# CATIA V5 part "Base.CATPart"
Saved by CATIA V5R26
Part number: Base
Bounding box of the stored display mesh (mm): x -23.876 to 23.876, y 0 to 88.9, z 0 to 54.102
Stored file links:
  D:\_Deepak\CATIA\CATIA V5 2015 Parts Files\EXE Files\Exercises\c13_catia_v5_6r2015_exr\C13Exr01_cat_v5-6r2015\Base_cat_v5-6r2015.CATPart
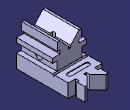
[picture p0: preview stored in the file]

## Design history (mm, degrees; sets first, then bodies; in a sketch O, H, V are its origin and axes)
Body1 (main body)
  Sketch1 on xy-plane, origin (0, 0, 0), H (1, 0, 0), V (0, 1, 0)
    line L1 (-23.876, 0) -> (23.876, 0)
    point P1 (-23.876, 0)
    point P2 (23.876, 0)
    construction line L2 (-23.876, 50.8) -> (23.876, 50.8)
    point P3 (-23.876, 50.8)
    point P4 (23.876, 50.8)
    line L3 (23.876, 0) -> (23.876, 72.898)
    point P5 (23.876, 72.898)
    line L4 (23.876, 72.898) -> (13.462, 72.898)
    point P6 (13.462, 72.898)
    line L5 (13.462, 72.898) -> (13.462, 77.724)
    point P7 (13.462, 77.724)
    line L6 (13.462, 77.724) -> (16.51, 77.724)
    point P8 (16.51, 77.724)
    line L7 (16.51, 77.724) -> (16.51, 88.9)
    point P9 (16.51, 88.9)
    line L8 (16.51, 88.9) -> (13.462, 88.9)
    point P10 (13.462, 88.9)
    line L9 (13.462, 88.9) -> (1.778, 77.724)
    point P11 (1.778, 77.724)
    line L10 (1.778, 77.724) -> (1.778, 72.898)
    point P12 (1.778, 72.898)
    line L11 (1.778, 72.898) -> (0, 72.898)
    point P13 (0, 72.898)
    point P14 (0, 72.898)
    point P15 (-1.778, 72.898)
    line L12 (-1.778, 72.898) -> (0, 72.898)
    point P16 (-1.778, 77.724)
    line L13 (-1.778, 77.724) -> (-1.778, 72.898)
    point P17 (-13.462, 88.9)
    line L14 (-13.462, 88.9) -> (-1.778, 77.724)
    point P18 (-16.51, 88.9)
    line L15 (-16.51, 88.9) -> (-13.462, 88.9)
    point P19 (-16.51, 77.724)
    line L16 (-16.51, 77.724) -> (-16.51, 88.9)
    point P20 (-13.462, 77.724)
    line L17 (-13.462, 77.724) -> (-16.51, 77.724)
    point P21 (-13.462, 72.898)
    line L18 (-13.462, 72.898) -> (-13.462, 77.724)
    point P22 (-23.876, 72.898)
    line L19 (-23.876, 72.898) -> (-13.462, 72.898)
    point P23 (-23.876, 50.8)
    point P24 (23.876, 50.8)
    construction line L20 (23.876, 50.8) -> (-23.876, 50.8)
    point P25 (-23.876, 0)
    line L21 (-23.876, 0) -> (-23.876, 72.898)
    length L1 = 47.752
    distance P2 V = 23.876
    distance L2 L1 = 50.8
    distance P5 L2 = 22.098
    distance L7 P1 = 40.386
    distance L5 P1 = 37.338
    distance L2 P7 = 26.924
    distance P9 L2 = 38.1
    distance P10 L3 = 10.414
    distance L10 L3 = 22.098
    distance L11 L2 = 22.098
    distance P11 L2 = 26.924
    horizontal: L1 H, L2 H, L4 H, L6 H, L8 H, L11 H
    coincidence: H L1, P13 V, P13 P14
    vertical: L3 V, L5 V, L7 V, L10 V
    symmetry: P13 P14 V, P12 P15 V, L11 L12 V, P11 P16 V, L10 L13 V, P10 P17 V, L9 L14 V, P9 P18 V, L8 L15 V, P8 P19 V, L7 L16 V, P7 P20 V, L6 L17 V, P6 P21 V, L5 L18 V, P5 P22 V, L4 L19 V, P4 P23 V, P3 P24 V, L2 L20 V, P2 P25 V, L3 L21 V
  Pad1: profile Sketch1, direction (0, 0, 1), length 19.05
  Sketch2 on face of Pad1, origin (23.876, 0, 0), H (0, 1, 0), V (0, 0, 1)
    point P1 (50.8, 19.05)
    line L1 (50.8, 19.05) -> (52.324, 16.4104)
    line L2 (52.324, 16.4104) -> (53.848, 19.05)
    line L3 (53.848, 19.05) -> (50.8, 19.05)
    reference projected line E1 (72.898, 19.05) -> (0, 19.05) from edge of Pad1
    length L2 = 3.048
    length L1 = 3.048
    distance P1 V = 50.8
    angle L1 L2 = 60
    horizontal: L3 H
    coincidence: L3 E1
  Pocket1: profile Sketch2, direction (-1, 0, 0), through (limit type 6)
  Sketch3 on face of Pad1, origin (0, 0, 0), H (1, 0, 0), V (0, 0, 1)
    line L1 (17.526, 19.05) -> (17.526, 31.75)
    point P1 (17.526, 19.05)
    point P2 (17.526, 31.75)
    line L2 (17.526, 31.75) -> (23.876, 31.75)
    point P3 (23.876, 31.75)
    line L3 (23.876, 31.75) -> (23.876, 38.1)
    point P4 (23.876, 38.1)
    line L4 (23.876, 38.1) -> (13.462, 38.1)
    point P5 (13.462, 38.1)
    line L5 (13.462, 38.1) -> (13.462, 42.926)
    point P6 (13.462, 42.926)
    line L6 (13.462, 42.926) -> (16.637, 42.926)
    point P7 (16.637, 42.926)
    line L7 (16.637, 42.926) -> (16.637, 54.102)
    point P8 (16.637, 54.102)
    reference projected line E1 (23.876, 19.05) -> (-23.876, 19.05) from edge of Pad1
    reference projected line E2 (23.876, 0) -> (23.876, 19.05) from edge of Pad1
    reference projected line E3 (-23.876, 19.05) -> (-23.876, 0) from edge of Pad1
    line L8 (16.637, 54.102) -> (13.462, 54.102)
    point P9 (13.462, 54.102)
    point P10 (1.651, 41.402)
    line L9 (1.651, 41.402) -> (1.651, 38.1)
    point P11 (1.651, 38.1)
    line L10 (1.651, 38.1) -> (0, 38.1)
    point P12 (0, 38.1)
    line L11 (1.651, 41.402) -> (13.462, 54.102)
    point P13 (-13.462, 54.102)
    point P14 (-1.651, 41.402)
    line L12 (-1.651, 41.402) -> (-13.462, 54.102)
    point P15 (0, 38.1)
    point P16 (-1.651, 38.1)
    line L13 (-1.651, 38.1) -> (0, 38.1)
    line L14 (-1.651, 41.402) -> (-1.651, 38.1)
    point P17 (-16.637, 54.102)
    line L15 (-16.637, 54.102) -> (-13.462, 54.102)
    point P18 (-16.637, 42.926)
    line L16 (-16.637, 42.926) -> (-16.637, 54.102)
    point P19 (-13.462, 42.926)
    line L17 (-13.462, 42.926) -> (-16.637, 42.926)
    point P20 (-13.462, 38.1)
    line L18 (-13.462, 38.1) -> (-13.462, 42.926)
    point P21 (-23.876, 38.1)
    line L19 (-23.876, 38.1) -> (-13.462, 38.1)
    point P22 (-23.876, 31.75)
    line L20 (-23.876, 31.75) -> (-23.876, 38.1)
    point P23 (-17.526, 31.75)
    line L21 (-17.526, 31.75) -> (-23.876, 31.75)
    point P24 (-17.526, 19.05)
    line L22 (-17.526, 19.05) -> (-17.526, 31.75)
    line L23 (-17.526, 19.05) -> (17.526, 19.05)
    distance V L1 = 17.526
    distance L2 H = 31.75
    distance L4 H = 38.1
    distance L6 H = 42.926
    distance L7 V = 16.637
    distance L5 E3 = 37.338
    distance V P9 = 13.462
    distance L8 H = 54.102
    distance L9 V = 1.651
    length L9 = 3.302
    vertical: L1 V, L3 V, L5 V, L7 V, L9 V
    horizontal: L2 H, L4 H, L6 H, L8 H, L10 H, L23 H
    coincidence: P1 E1, L3 E2, P11 L4, P12 V, P12 P15
    symmetry: P9 P13 V, P10 P14 V, L11 L12 V, P12 P15 V, P11 P16 V, L10 L13 V, L9 L14 V, P8 P17 V, L8 L15 V, P7 P18 V, L7 L16 V, P6 P19 V, L6 L17 V, P5 P20 V, L5 L18 V, P4 P21 V, L4 L19 V, P3 P22 V, L3 L20 V, P2 P23 V, L2 L21 V, P1 P24 V, L1 L22 V
  Pad2: profile Sketch3, direction (0, 1, 0), length 50.8
  Sketch4 on face of Pad1, origin (4.0235, 27.8102, 0), H (1, 0, 0), V (0, -1, 0)
    point P1 (-4.0235, 2.4102)
    reference projected line E1 (13.5025, -22.9898) -> (-21.5495, -22.9898) from edge of Pad2
    reference intersected line E2 through (-4.0235, 0) direction (0, 1) from yz-plane
    distance P1 E1 = 25.4
    coincidence: E2 P1
  Hole1: placed by Sketch4, at (0, 25.4, 0) direction (0, 0, 1), diameter 7.874, depth 54.102
  Sketch5 on face of Pad2, origin (17.526, 12.3932, 23.5222), H (0, 1, 0), V (0, 0, 1)
    point P1 (13.0068, 1.8778)
    reference projected line E1 (-12.3932, 8.2278) -> (-12.3932, -4.4722) from edge of Pad2
    reference projected line E2 (-12.3932, -23.5222) -> (60.5048, -23.5222) from edge of Pad1
    distance E1 P1 = 25.4
    distance E2 P1 = 25.4
  Hole2: placed by Sketch5, at (17.526, 25.4, 25.4) direction (-1, 0, 0), diameter 9.652, depth 54.102
  Sketch6 on face of Pad1, origin (0, 0, 19.05), H (1, 0, 0), V (0, 1, 0)
    construction line L1 (-23.876, 63.373) -> (23.876, 63.373)
    point P1 (-23.876, 63.373)
    point P2 (23.876, 63.373)
    reference projected line E1 (23.876, 53.848) -> (-23.876, 53.848) from edge of Pocket1
    construction line L2 (-12.7, 63.373) -> (12.7, 63.373)
    point P3 (-12.7, 63.373)
    line L3 (-12.7, 66.548) -> (12.7, 66.548)
    line L4 (12.7, 60.198) -> (-12.7, 60.198)
    arc A1 centre (12.7, 63.373) radius 3.175 from (12.7, 66.548) to (12.7, 60.198) cw
    arc A2 centre (-12.7, 63.373) radius 3.175 from (-12.7, 60.198) to (-12.7, 66.548) cw
    reference projected line E2 (23.876, 72.898) -> (23.876, 0) from edge of Pad1
    reference projected line E3 (-23.876, 72.898) -> (-23.876, 0) from edge of Pad1
    reference projected line E4 (-23.876, 72.898) -> (-23.876, 0) from edge of Pad1
    distance E1 L1 = 9.525
    radius A1 = 3.175
    distance A1 A2 = 31.75
    distance P3 E4 = 11.176
    horizontal: L1 H, L2 H
    coincidence: P3 L1, P2 E2, P1 E3
    tangency: A1 L3, A2 L3, A1 L4, A2 L4
    parallelism: L2 L3
  Pocket2: profile Sketch6, direction (0, 0, -1), length 0.762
